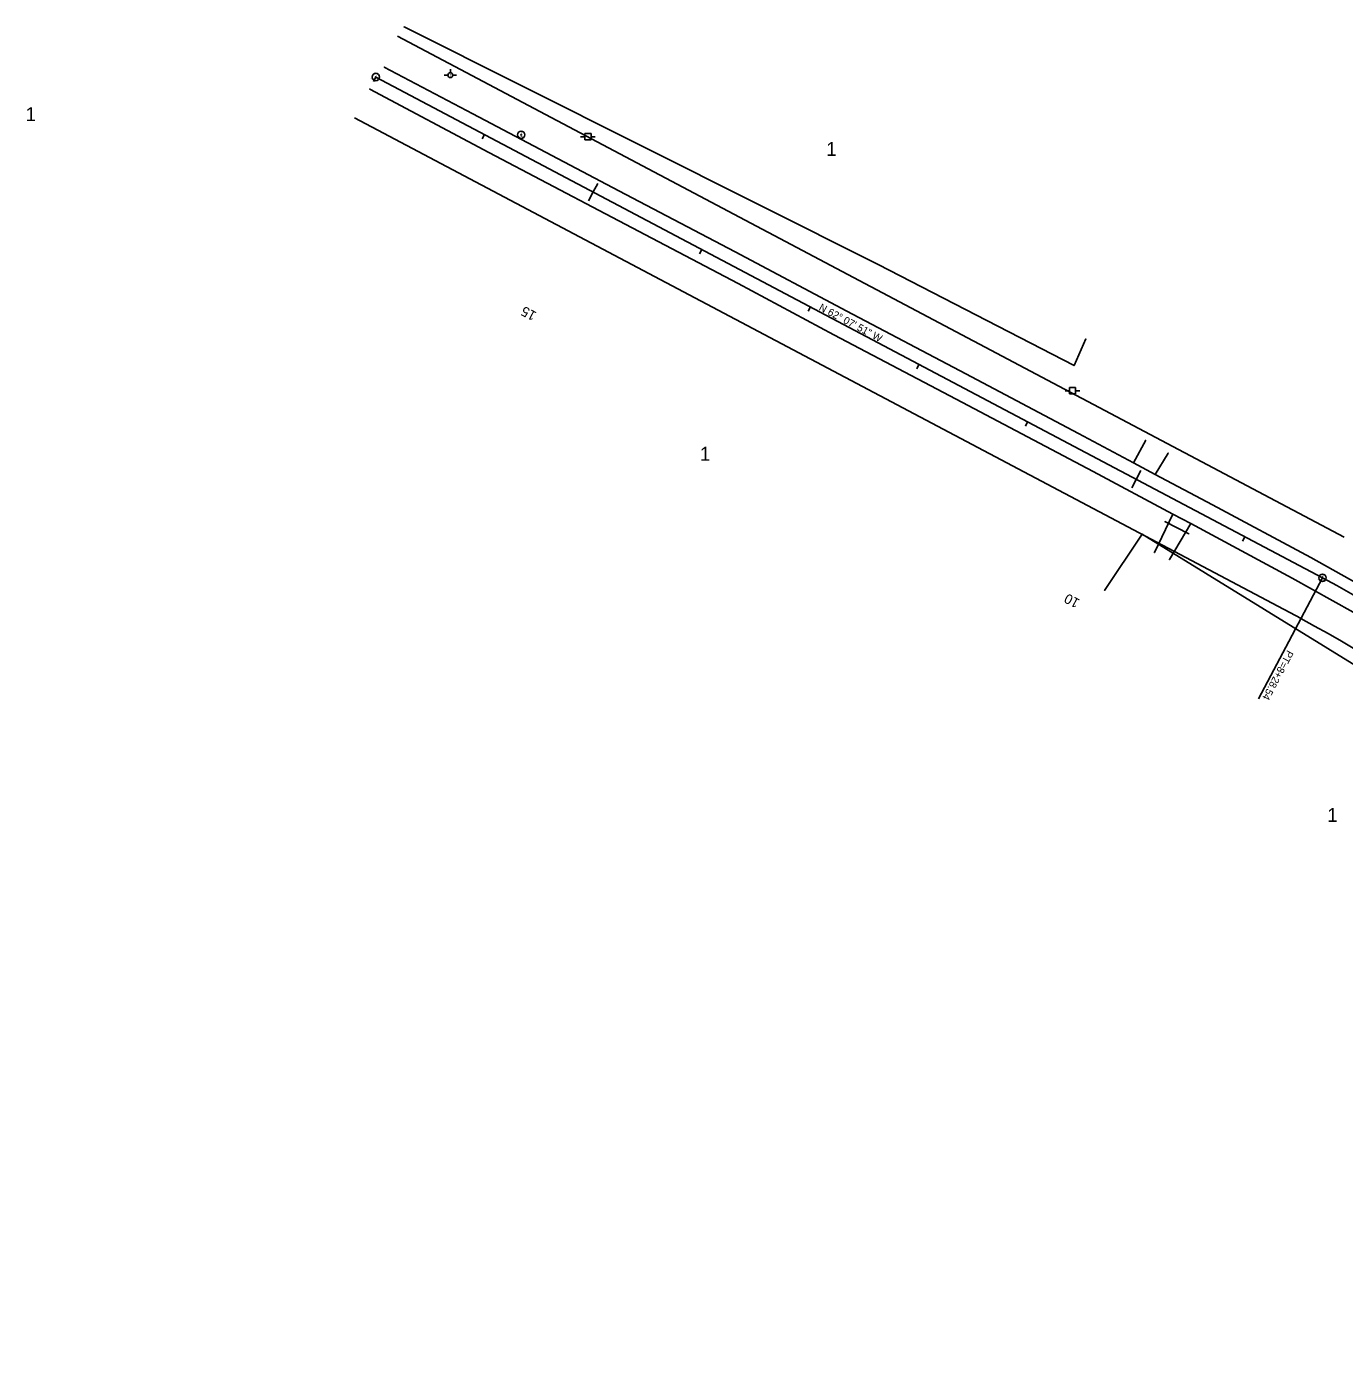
# Model space of a CAD drawing. Extents: x 2519952 to 2531965, y 848341 to 887632.
# Drawn here: x 2522647 to 2523719, y 857409 to 858504 of the extents above; entities that cross this region are included whole.
import ezdxf

# ---------------------------------------------------------------- set-up
doc = ezdxf.new("R2010")
doc.units = 0
for name, color, linetype in [('RD_EX_DR_Pipe', 7, 'Continuous'), ('RD_EX_Driveway', 7, 'Continuous'), ('RD_EX_DV_Prop', 7, 'Continuous'), ('RD_EX_DV_TX_Prop', 7, 'Continuous'), ('RD_EX_Road', 7, 'Continuous'), ('RD_EX_RW', 7, 'Continuous'), ('RD_EX_UT', 7, 'Continuous'), ('RD_EX_VEG', 7, 'Continuous'), ('RD_HC_Cl', 7, 'Continuous'), ('RD_HC_Data', 7, 'Continuous'), ('RD_HC_Data_Tic', 7, 'Continuous'), ('RD_HC_Survey_txCode', 7, 'Continuous'), ('RD_HC_TX_Sta50', 7, 'Continuous'), ('RD_HC_txCode', 7, 'Continuous'), ('RD_SMD_Locator', 7, 'Continuous')]:
    doc.layers.add(name, color=color, linetype=linetype)

msp = doc.modelspace()

# ---------------------------------------------------------------- linework, layer by layer
at = {"layer": 'RD_EX_DR_Pipe'}
msp.add_line((2523592.5, 858092.1), (2523572.9, 858102.1), dxfattribs=at)
at = {"layer": 'RD_EX_Driveway'}
for p, q in [((2523557.4, 858168.2), (2523547.4, 858149.9)), ((2523564.9, 858140.4), (2523575.6, 858157.8)), ((2523579.4, 858108.2), (2523564.4, 858076.8)), ((2523593.9, 858100.6), (2523576.6, 858071.2))]:
    msp.add_line(p, q, dxfattribs=at)
at = {"layer": 'RD_EX_DV_Prop'}
for p, q in [((2523718.8, 858089.4), (2522948.4, 858496.8)), ((2523683.7, 858023.1), (2522913.3, 858430.5))]:
    msp.add_line(p, q, dxfattribs=at)
msp.add_arc((2523254.8, 857212.1), 917.4, 12.4185, 62.1307, dxfattribs=at)
at = {"layer": 'RD_EX_Road'}
for points in [[(2524083.8, 857706.1), (2524041.2, 857771.8), (2523995.8, 857831.1), (2523964.7, 857866.8), (2523931.4, 857900.9), (2523904.1, 857926.6), (2523830.2, 857986.6), (2523793.1, 858012.8), (2523736.6, 858047.7), (2523691.7, 858072.9), (2523611.6, 858115.8), (2523564.9, 858140.4), (2523547.4, 858149.9), (2523502.6, 858173.7), (2523410.9, 858222.2), (2523314, 858273.2), (2523223.1, 858321.4), (2523128.6, 858371), (2523009.6, 858433.8), (2522937.6, 858471.8)], [(2524164.7, 857466.2), (2524145.4, 857525.1), (2524117.7, 857595.2), (2524087.6, 857655.7), (2524082.1, 857665.7), (2524023.3, 857759), (2523979, 857816.7), (2523948.4, 857852.2), (2523907.3, 857893.7), (2523862.7, 857933.5), (2523814.4, 857971), (2523773.2, 857999.7), (2523726.2, 858028.5), (2523676.6, 858056.1), (2523593.9, 858100.6), (2523579.4, 858108.2), (2523514.5, 858142.7), (2523403, 858201.7), (2523303.5, 858254.1), (2523225.6, 858295.6), (2523117.7, 858352.3), (2523022.8, 858402.3), (2522925.8, 858453.9)]]:
    msp.add_lwpolyline(points, dxfattribs=at)
at = {"layer": 'RD_EX_RW'}
for p, q in [((2523718.8, 858089.4), (2522948.4, 858496.8)), ((2523718.8, 858089.4), (2522948.4, 858496.8)), ((2523683.7, 858023.1), (2522913.3, 858430.5))]:
    msp.add_line(p, q, dxfattribs=at)
msp.add_arc((2523254.8, 857212.1), 917.4, 12.4185, 62.1308, dxfattribs=at)
at = {"layer": 'RD_EX_UT'}
for p, q in [((2522986.4, 858465.2), (2522989.4, 858465.2)), ((2522991.4, 858470.2), (2522991.4, 858467.2)), ((2522993.4, 858465.2), (2522996.4, 858465.2)), ((2523097.4, 858415.1), (2523100.9, 858415.1)), ((2523105.9, 858417.7), (2523100.9, 858417.7)), ((2523100.9, 858417.7), (2523100.9, 858412.7)), ((2523100.9, 858412.7), (2523105.9, 858412.7)), ((2523105.8, 858415.1), (2523109.4, 858415.1)), ((2523105.9, 858412.7), (2523105.9, 858417.7)), ((2523500.2, 858211.1), (2523495.2, 858211.1)), ((2523495.2, 858211.1), (2523495.2, 858206.1)), ((2523500.2, 858206.1), (2523500.2, 858211.1)), ((2523491.7, 858208.5), (2523495.2, 858208.5)), ((2523495.2, 858206.1), (2523500.2, 858206.1)), ((2523500.1, 858208.5), (2523503.7, 858208.5))]:
    msp.add_line(p, q, dxfattribs=at)
msp.add_circle((2522991.4, 858465.2), 2, dxfattribs=at)
at = {"layer": 'RD_EX_VEG'}
for points in [[(2523508.6, 858250.7), (2523499, 858229), (2523339.6, 858311.3), (2522953.7, 858504.4)], [(2524119.6, 857524.8), (2524064.8, 857652.4), (2523973.6, 857801.1), (2523957.8, 857795.2), (2523784.7, 857949.9), (2523705.5, 857998.7), (2523554.5, 858091.9), (2523523.9, 858046.1)]]:
    msp.add_lwpolyline(points, dxfattribs=at)
at = {"layer": 'RD_HC_Cl'}
msp.add_line((2523701.2, 858056.3), (2522930.8, 858463.7), dxfattribs=at)
msp.add_arc((2523254.8, 857212.1), 954.9, 12.4185, 62.1308, dxfattribs=at)
at = {"layer": 'RD_HC_Data'}
msp.add_line((2523701.2, 858056.3), (2523649.2, 857957.9), dxfattribs=at)
for centre, radius in [((2522930.8, 858463.7), 3), ((2522930.8, 858463.7), 0.282), ((2523049, 858416.7), 3), ((2523049, 858416.7), 0.282), ((2523701.2, 858056.3), 3), ((2523701.2, 858056.3), 0.282)]:
    msp.add_circle(centre, radius, dxfattribs=at)
at = {"layer": 'RD_HC_Data_Tic'}
for p, q in [((2522930.8, 858463.7), (2522929, 858460.1)), ((2523019.2, 858416.9), (2523017.4, 858413.4)), ((2523107.6, 858370.2), (2523111.4, 858377.2)), ((2523107.6, 858370.2), (2523103.9, 858363.1)), ((2523196, 858323.4), (2523194.2, 858319.9)), ((2523284.4, 858276.7), (2523282.6, 858273.1)), ((2523372.8, 858229.9), (2523371, 858226.4)), ((2523461.2, 858183.2), (2523459.4, 858179.6)), ((2523549.6, 858136.4), (2523545.9, 858129.4)), ((2523549.6, 858136.4), (2523553.4, 858143.5)), ((2523638, 858089.7), (2523636.2, 858086.2))]:
    msp.add_line(p, q, dxfattribs=at)
at = {"layer": 'RD_SMD_Locator'}
for centre in [(2522953.7, 858504.4), (2522930.8, 858463.7), (2522937.6, 858471.8), (2522925.8, 858453.9), (2523009.6, 858433.8), (2523049, 858416.7), (2523022.8, 858402.3), (2523128.6, 858371), (2523117.7, 858352.3), (2523223.1, 858321.4), (2523339.6, 858311.3), (2523225.6, 858295.6), (2523314, 858273.2), (2523303.5, 858254.1), (2523508.6, 858250.7), (2523410.9, 858222.2), (2523499, 858229), (2523403, 858201.7), (2523502.6, 858173.7), (2523557.4, 858168.2), (2523575.6, 858157.8), (2523547.4, 858149.9), (2523547.4, 858149.9), (2523514.5, 858142.7), (2523564.9, 858140.4), (2523564.9, 858140.4), (2523611.6, 858115.8), (2523572.9, 858102.1), (2523579.4, 858108.2), (2523579.4, 858108.2), (2523554.5, 858091.9), (2523592.5, 858092.1), (2523593.9, 858100.6), (2523593.9, 858100.6), (2523564.4, 858076.8), (2523576.6, 858071.2), (2523691.7, 858072.9), (2523523.9, 858046.1), (2523676.6, 858056.1), (2523701.2, 858056.3), (2523705.5, 857998.7)]:
    msp.add_circle(centre, 0.001, dxfattribs=at)

# ---------------------------------------------------------------- texts
at = {"layer": 'RD_EX_DV_TX_Prop'}
for p in [(2522645.7, 858427.8), (2523297.3, 858399.5), (2523194.6, 858151.6), (2523705, 857857.7)]:
    msp.add_text('1', height=11.3, dxfattribs=at).set_placement(p)
at = {"layer": 'RD_EX_UT'}
msp.add_text('T', height=2, dxfattribs=at).set_placement((2522990.7, 858464.1))
at = {"layer": 'RD_HC_Data'}
msp.add_text('PT=8+28.54', height=6, rotation=242.1308, dxfattribs=at).set_placement((2523672.6, 857997.9))
at = {"layer": 'RD_HC_Survey_txCode'}
msp.add_text('N 62%%d 07\' 51" W', height=6, rotation=332.1308, dxfattribs=at).set_placement((2523290.8, 858274.4))
at = {"layer": 'RD_HC_TX_Sta50'}
for s, p in [('15', (2523062.2, 858272)), ('10', (2523504.3, 858038.3))]:
    msp.add_text(s, height=8, rotation=152.1308, dxfattribs=at).set_placement(p)
at = {"layer": 'RD_HC_txCode'}
for s, p in [('POT 17+00.00', (2522925.8, 858461.7)), ('20', (2522930.1, 858464.7)), ('8', (2523048.8, 858417.7)), ('CP 8 MSC', (2523045.4, 858414.7)), ('18', (2523700.8, 858057.3)), ('PT 8+28.54', (2523697, 858054.3))]:
    msp.add_text(s, height=1, dxfattribs=at).set_placement(p)

doc.saveas('drawing.dxf')
